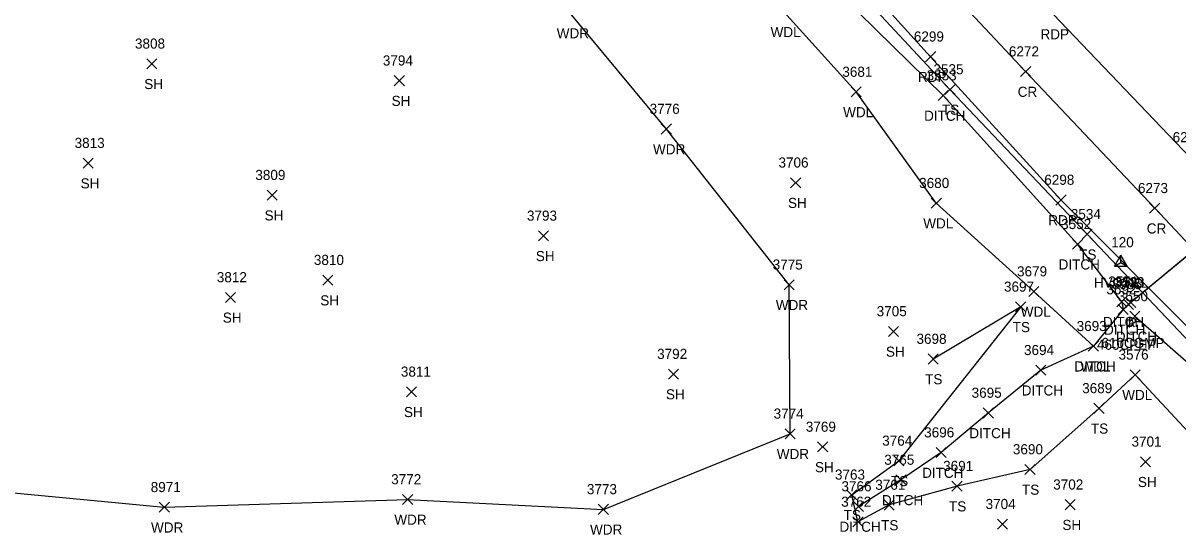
# Model space of a CAD drawing. Extents: x 1482574 to 1485769, y 580696 to 595649.
# Drawn here: x 1483954 to 1484182.5, y 582869.5 to 582970.7 of the extents above; entities that cross this region are included whole.
import ezdxf

# ---------------------------------------------------------------- set-up
doc = ezdxf.new("R2010")
doc.units = 0
for name, color, linetype in [('C_A', 7, 'Continuous'), ('C_I', 7, 'Continuous'), ('CPSM', 7, 'Continuous'), ('D_A', 7, 'Continuous'), ('D_C', 7, 'Continuous'), ('D_I', 7, 'Continuous'), ('D_TIC', 7, 'Continuous'), ('DCP', 7, 'Continuous'), ('DD', 7, 'Continuous'), ('L_A', 7, 'Continuous'), ('L_I', 7, 'Continuous'), ('L_TIC', 7, 'Continuous'), ('LABL', 7, 'Continuous'), ('LAWA', 7, 'Continuous'), ('LELB', 7, 'Continuous'), ('P_A', 7, 'Continuous'), ('P_I', 7, 'Continuous'), ('P_TIC', 7, 'Continuous'), ('PET', 7, 'Continuous'), ('PRC', 7, 'Continuous')]:
    doc.layers.add(name, color=color, linetype=linetype)

msp = doc.modelspace()

# ---------------------------------------------------------------- linework, layer by layer
at = {"layer": 'CPSM'}
for p, q in [((1484169.92, 582922.65), (1484171.17, 582924.82)), ((1484172.42, 582922.65), (1484171.17, 582924.82)), ((1484171.17, 582923.37), (1484171.17, 582924.82)), ((1484169.92, 582922.65), (1484171.17, 582923.37)), ((1484169.92, 582922.65), (1484172.42, 582922.65)), ((1484171.17, 582923.37), (1484171.17, 582923.37)), ((1484171.17, 582923.37), (1484172.42, 582922.65))]:
    msp.add_line(p, q, dxfattribs=at)
at = {"layer": 'D_TIC'}
for points in [[(1484135.02, 582955.39), (1484137.02, 582957.39)], [(1484137.02, 582955.39), (1484135.02, 582957.39)], [(1484161.64, 582925.97), (1484163.64, 582927.97)], [(1484163.64, 582925.97), (1484161.64, 582927.97)], [(1484170.4, 582914.6), (1484172.4, 582916.6)], [(1484172.4, 582914.6), (1484170.4, 582916.6)], [(1484171.69, 582914.09), (1484173.69, 582916.09)], [(1484173.69, 582914.09), (1484171.69, 582916.09)], [(1484172.17, 582914.45), (1484174.17, 582916.45)], [(1484174.17, 582914.45), (1484172.17, 582916.45)], [(1484170.63, 582913.07), (1484172.62, 582915.07)], [(1484172.62, 582913.07), (1484170.63, 582915.07)], [(1484172.95, 582911.7), (1484174.95, 582913.7)], [(1484174.95, 582911.7), (1484172.95, 582913.7)], [(1484164.75, 582905.79), (1484166.75, 582907.79)], [(1484166.75, 582905.79), (1484164.75, 582907.79)], [(1484154.34, 582901.04), (1484156.34, 582903.04)], [(1484156.34, 582901.04), (1484154.34, 582903.04)], [(1484143.98, 582892.59), (1484145.98, 582894.59)], [(1484145.98, 582892.59), (1484143.98, 582894.59)], [(1484134.64, 582884.75), (1484136.64, 582886.75)], [(1484136.64, 582884.75), (1484134.64, 582886.75)], [(1484126.69, 582879.34), (1484128.69, 582881.34)], [(1484128.69, 582879.34), (1484126.69, 582881.34)], [(1484118.28, 582874.08), (1484120.28, 582876.08)], [(1484120.28, 582874.08), (1484118.28, 582876.08)]]:
    msp.add_lwpolyline(points, dxfattribs=at)
at = {"layer": 'DCP'}
for points in [[(1484172.69, 582915.09), (1484207.11, 582943.53)], [(1484203.91, 582940.91), (1484173.17, 582915.45)]]:
    msp.add_lwpolyline(points, dxfattribs=at)
at = {"layer": 'DD'}
for points in [[(1484171.4, 582915.6), (1484162.64, 582926.97), (1484136.02, 582956.39), (1484105.95, 582985.95), (1484078.03, 583016.39), (1484050.41, 583045.09), (1484023.91, 583073.18), (1484012.19, 583086.75)], [(1484171.4, 582915.6), (1484171.62, 582914.07)], [(1484171.62, 582914.07), (1484165.75, 582906.79), (1484155.34, 582902.04), (1484144.98, 582893.59), (1484135.64, 582885.75), (1484127.69, 582880.34), (1484119.28, 582875.08)], [(1484400.87, 582726.9), (1484383.65, 582732.27), (1484351.97, 582747.1), (1484327.02, 582760.95), (1484298.61, 582786.76), (1484268.65, 582815.14), (1484241.89, 582844.67), (1484214.72, 582873.05), (1484187.35, 582900.96), (1484173.95, 582912.7)]]:
    msp.add_lwpolyline(points, dxfattribs=at)
at = {"layer": 'L_TIC'}
for points in [[(1483978.5, 582961.67), (1483980.5, 582963.67)], [(1483980.5, 582961.67), (1483978.5, 582963.67)], [(1484027.45, 582958.33), (1484029.45, 582960.33)], [(1484029.45, 582958.33), (1484027.45, 582960.33)], [(1484117.83, 582956.1), (1484119.83, 582958.09)], [(1484119.83, 582956.1), (1484117.83, 582958.09)], [(1484136.38, 582956.59), (1484138.38, 582958.59)], [(1484138.38, 582956.59), (1484136.38, 582958.59)], [(1484080.28, 582948.76), (1484082.28, 582950.76)], [(1484082.28, 582948.76), (1484080.28, 582950.76)], [(1483965.92, 582942.02), (1483967.92, 582944.02)], [(1483967.92, 582942.02), (1483965.92, 582944.02)], [(1484105.85, 582938.14), (1484107.85, 582940.14)], [(1484107.85, 582938.14), (1484105.85, 582940.14)], [(1484002.32, 582935.68), (1484004.32, 582937.68)], [(1484004.32, 582935.68), (1484002.32, 582937.68)], [(1484133.68, 582934.09), (1484135.68, 582936.09)], [(1484135.68, 582934.09), (1484133.68, 582936.09)], [(1484055.96, 582927.63), (1484057.96, 582929.63)], [(1484057.96, 582927.63), (1484055.96, 582929.63)], [(1484163.54, 582927.94), (1484165.54, 582929.94)], [(1484165.54, 582927.94), (1484163.54, 582929.94)], [(1484013.33, 582918.87), (1484015.33, 582920.87)], [(1484015.33, 582918.87), (1484013.33, 582920.87)], [(1484104.57, 582917.95), (1484106.57, 582919.95)], [(1484106.57, 582917.95), (1484104.57, 582919.95)], [(1484152.96, 582916.61), (1484154.96, 582918.61)], [(1484154.96, 582916.61), (1484152.96, 582918.61)], [(1484152.96, 582916.61), (1484154.96, 582918.61)], [(1484154.96, 582916.61), (1484152.96, 582918.61)], [(1483994.04, 582915.45), (1483996.04, 582917.45)], [(1483996.04, 582915.45), (1483994.04, 582917.45)], [(1484150.38, 582913.58), (1484152.38, 582915.58)], [(1484152.38, 582913.58), (1484150.38, 582915.58)], [(1484125.22, 582908.72), (1484127.22, 582910.72)], [(1484127.22, 582908.72), (1484125.22, 582910.72)], [(1484164.75, 582905.79), (1484166.75, 582907.79)], [(1484166.75, 582905.79), (1484164.75, 582907.79)], [(1484133.06, 582903.26), (1484135.06, 582905.26)], [(1484135.06, 582903.26), (1484133.06, 582905.26)], [(1484081.71, 582900.28), (1484083.71, 582902.27)], [(1484083.71, 582900.28), (1484081.71, 582902.27)], [(1484173.04, 582900.15), (1484175.04, 582902.15)], [(1484175.04, 582900.15), (1484173.04, 582902.15)], [(1484029.88, 582896.77), (1484031.88, 582898.77)], [(1484031.88, 582896.77), (1484029.88, 582898.77)], [(1484165.86, 582893.5), (1484167.86, 582895.5)], [(1484167.86, 582893.5), (1484165.86, 582895.5)], [(1484104.76, 582888.47), (1484106.76, 582890.47)], [(1484106.76, 582888.47), (1484104.76, 582890.47)], [(1484111.19, 582885.87), (1484113.19, 582887.87)], [(1484113.19, 582885.87), (1484111.19, 582887.87)], [(1484126.29, 582883.11), (1484128.29, 582885.11)], [(1484128.29, 582883.11), (1484126.29, 582885.11)], [(1484175.07, 582882.93), (1484177.07, 582884.93)], [(1484177.07, 582882.93), (1484175.07, 582884.93)], [(1484152.22, 582881.41), (1484154.22, 582883.41)], [(1484154.22, 582881.41), (1484152.22, 582883.41)], [(1484137.78, 582878.11), (1484139.78, 582880.11)], [(1484139.78, 582878.11), (1484137.78, 582880.11)], [(1484029.1, 582875.49), (1484031.1, 582877.48)], [(1484031.1, 582875.49), (1484029.1, 582877.48)], [(1484116.94, 582876.4), (1484118.94, 582878.4)], [(1484118.94, 582876.4), (1484116.94, 582878.4)], [(1483980.96, 582873.93), (1483982.96, 582875.93)], [(1483982.96, 582873.93), (1483980.96, 582875.93)], [(1484067.82, 582873.52), (1484069.82, 582875.52)], [(1484069.82, 582873.52), (1484067.82, 582875.52)], [(1484124.35, 582874.38), (1484126.35, 582876.38)], [(1484126.35, 582874.38), (1484124.35, 582876.38)], [(1484160.15, 582874.45), (1484162.15, 582876.44)], [(1484162.15, 582874.45), (1484160.15, 582876.44)], [(1484118.18, 582871.03), (1484120.18, 582873.03)], [(1484120.18, 582871.03), (1484118.18, 582873.03)], [(1484146.77, 582870.58), (1484148.77, 582872.58)], [(1484148.77, 582870.58), (1484146.77, 582872.58)]]:
    msp.add_lwpolyline(points, dxfattribs=at)
at = {"layer": 'LABL'}
msp.add_lwpolyline([(1483947.92, 582878.18), (1483981.96, 582874.93)], dxfattribs=at)
at = {"layer": 'LAWA'}
for points in [[(1484030.1, 582876.48), (1484068.82, 582874.52), (1484105.76, 582889.47), (1484105.57, 582918.95), (1484081.28, 582949.76), (1484062.23, 582972.71), (1484033.59, 583003.27), (1484005.46, 583038.35), (1483989.3, 583058.08), (1483962.79, 583084.49), (1483933.09, 583114.83), (1483908.74, 583144.04), (1483882.23, 583166.93), (1483868.61, 583172.26)], [(1484153.96, 582917.61), (1484134.68, 582935.09), (1484118.83, 582957.09), (1484104.49, 582972.93), (1484091.89, 582987.87), (1484079.75, 582997.92), (1484068.28, 583011), (1484047.87, 583032.86), (1484030.91, 583051.96), (1484004.4, 583078.79)], [(1484153.96, 582917.61), (1484165.75, 582906.79)], [(1484191.87, 582821.82), (1484229.21, 582818.01), (1484245.75, 582826.08), (1484219.74, 582845.54), (1484205.23, 582866.51), (1484188.09, 582886.02), (1484174.04, 582901.15)], [(1483981.96, 582874.93), (1484030.1, 582876.48)]]:
    msp.add_lwpolyline(points, dxfattribs=at)
at = {"layer": 'LELB'}
for points in [[(1484402.9, 582726.21), (1484402.79, 582730.01), (1484384.34, 582736.92), (1484350.52, 582752.18), (1484323.04, 582770.42), (1484293.61, 582794.8), (1484265.96, 582821.75), (1484239.84, 582849.66), (1484213.41, 582877.57), (1484187.41, 582904.81), (1484164.54, 582928.94), (1484137.38, 582957.59), (1484109.3, 582987.71), (1484082.7, 583016.6), (1484054.89, 583044.87), (1484027.97, 583073.07), (1484014.36, 583088.28)], [(1484151.38, 582914.58), (1484127.29, 582884.11)], [(1484151.38, 582914.58), (1484134.06, 582904.26)], [(1484166.86, 582894.5), (1484174.04, 582901.15)], [(1484166.86, 582894.5), (1484153.22, 582882.41), (1484138.78, 582879.11)], [(1484125.35, 582875.38), (1484119.18, 582872.03), (1484117.94, 582877.4), (1484127.29, 582884.11)], [(1484138.78, 582879.11), (1484125.35, 582875.38)]]:
    msp.add_lwpolyline(points, dxfattribs=at)
at = {"layer": 'P_TIC'}
for points in [[(1484132.56, 582963.07), (1484134.56, 582965.07)], [(1484134.56, 582963.07), (1484132.56, 582965.07)], [(1484151.35, 582960.13), (1484153.35, 582962.13)], [(1484153.35, 582960.13), (1484151.35, 582962.13)], [(1484158.34, 582934.73), (1484160.34, 582936.73)], [(1484160.34, 582934.73), (1484158.34, 582936.73)], [(1484176.88, 582933.09), (1484178.88, 582935.09)], [(1484178.88, 582933.09), (1484176.88, 582935.09)]]:
    msp.add_lwpolyline(points, dxfattribs=at)
at = {"layer": 'PET'}
for points in [[(1484491.08, 582753.94), (1484493.22, 582746.26), (1484462.76, 582739.1), (1484431.88, 582736.4), (1484400.51, 582737.99), (1484369.56, 582746.76), (1484340.37, 582760.44), (1484314.77, 582778.92), (1484290.06, 582800.8), (1484263.27, 582827.56), (1484237.31, 582854.83), (1484211.32, 582882.47), (1484185.75, 582909.27), (1484159.34, 582935.73), (1484133.56, 582964.07), (1484107.83, 582992.49), (1484081.64, 583020.87), (1484054.98, 583048.7), (1484028.69, 583076.2), (1484015.92, 583089.84)], [(1484488.73, 582762.43), (1484458.42, 582759.47), (1484428.1, 582761.56), (1484397.39, 582767.41), (1484367.33, 582777), (1484339.02, 582792.83), (1484318.92, 582808.53), (1484293.05, 582832.28), (1484266.16, 582858.48), (1484239.66, 582886.48), (1484211.15, 582916.1), (1484184.88, 582944.15), (1484157.81, 582972.51), (1484130.84, 583000.7), (1484106.21, 583027.51), (1484077.55, 583057.77), (1484051.19, 583086.4)]]:
    msp.add_lwpolyline(points, dxfattribs=at)
at = {"layer": 'PRC'}
msp.add_lwpolyline([(1484049.41, 583070.99), (1484075.46, 583043.5), (1484101.38, 583015.76), (1484126.34, 582988.92), (1484152.35, 582961.13), (1484177.88, 582934.09), (1484203.24, 582907.12), (1484228.69, 582880.03), (1484254.53, 582852.85), (1484280.74, 582825.88), (1484302.69, 582805.16), (1484325.66, 582786.45), (1484351.27, 582770.37), (1484379.25, 582758.35), (1484409.57, 582750.74), (1484442.81, 582748.51), (1484469.16, 582749.53), (1484491.08, 582753.94)], dxfattribs=at)

# ---------------------------------------------------------------- texts
at = {"layer": 'C_A'}
msp.add_text('HVCTRL', height=2, dxfattribs=at).set_placement((1484165.86, 582918.37))
at = {"layer": 'C_I'}
msp.add_text('120', height=2, dxfattribs=at).set_placement((1484169.28, 582926.37))
at = {"layer": 'D_A'}
for s, p in [('DITCH', (1484132.26, 582951.39)), ('DITCH', (1484158.88, 582921.97)), ('DITCH', (1484167.63, 582910.6)), ('DITCH', (1484167.86, 582909.07)), ('P', (1484172.06, 582910.09)), ('P', (1484172.55, 582910.45)), ('DITCH', (1484170.19, 582907.7)), ('DITCH', (1484161.99, 582901.79)), ('DITCH', (1484151.58, 582897.04)), ('DITCH', (1484141.21, 582888.59)), ('DITCH', (1484131.88, 582880.75)), ('DITCH', (1484123.92, 582875.34)), ('DITCH', (1484115.52, 582870.08))]:
    msp.add_text(s, height=2, dxfattribs=at).set_placement(p)
at = {"layer": 'D_C'}
for s, p in [('460CPEP', (1484166.46, 582906.09)), ('610CGMP', (1484167.34, 582906.45))]:
    msp.add_text(s, height=2, dxfattribs=at).set_placement(p)
at = {"layer": 'D_I'}
for s, p in [('3553', (1484132.76, 582959.39)), ('3552', (1484159.38, 582929.97)), ('3551', (1484168.71, 582918.6)), ('8985', (1484169.43, 582918.09)), ('3523', (1484169.91, 582918.45)), ('3692', (1484168.32, 582917.07)), ('3550', (1484170.61, 582915.7)), ('3693', (1484162.44, 582909.79)), ('3694', (1484152.03, 582905.04)), ('3695', (1484141.67, 582896.59)), ('3696', (1484132.28, 582888.75)), ('3765', (1484124.38, 582883.34)), ('3766', (1484115.92, 582878.08))]:
    msp.add_text(s, height=2, dxfattribs=at).set_placement(p)
at = {"layer": 'L_A'}
for s, p in [('WDR', (1484059.59, 582967.71)), ('WDL', (1484101.9, 582967.94)), ('SH', (1483977.99, 582957.67)), ('SH', (1484026.93, 582954.33)), ('TS', (1484135.79, 582952.59)), ('WDL', (1484116.25, 582952.09)), ('WDR', (1484078.64, 582944.76)), ('SH', (1483965.41, 582938.02)), ('SH', (1484105.34, 582934.14)), ('SH', (1484001.8, 582931.68)), ('WDL', (1484132.1, 582930.09)), ('SH', (1484055.45, 582923.63)), ('TS', (1484162.95, 582923.94)), ('SH', (1484012.82, 582914.87)), ('WDR', (1484102.93, 582913.95)), ('SH', (1483993.53, 582911.45)), ('WDL', (1484151.38, 582912.61)), ('WDL', (1484151.38, 582912.61)), ('TS', (1484149.79, 582909.58)), ('SH', (1484124.71, 582904.72)), ('WDL', (1484163.17, 582901.79)), ('TS', (1484132.47, 582899.26)), ('SH', (1484081.2, 582896.28)), ('WDL', (1484171.46, 582896.15)), ('SH', (1484029.37, 582892.77)), ('TS', (1484165.27, 582889.5)), ('WDR', (1484103.12, 582884.47)), ('SH', (1484110.68, 582881.87)), ('TS', (1484125.7, 582879.11)), ('TS', (1484151.63, 582877.41)), ('SH', (1484174.56, 582878.93)), ('TS', (1484116.35, 582872.4)), ('TS', (1484137.19, 582874.11)), ('WDR', (1484027.47, 582871.48)), ('TS', (1484123.76, 582870.38)), ('SH', (1484159.63, 582870.44)), ('WDR', (1483979.33, 582869.93)), ('WDR', (1484066.18, 582869.52))]:
    msp.add_text(s, height=2, dxfattribs=at).set_placement(p)
at = {"layer": 'L_I'}
for s, p in [('3808', (1483976.16, 582965.67)), ('3794', (1484025.19, 582962.33)), ('3681', (1484116.09, 582960.09)), ('3535', (1484134.12, 582960.59)), ('3776', (1484077.97, 582952.76)), ('3813', (1483964.22, 582946.02)), ('3706', (1484103.46, 582942.14)), ('3809', (1483999.97, 582939.68)), ('3680', (1484131.29, 582938.09)), ('3534', (1484161.29, 582931.94)), ('3793', (1484053.7, 582931.63)), ('3810', (1484011.55, 582922.87)), ('3775', (1484102.31, 582921.95)), ('3679', (1484150.65, 582920.61)), ('3679', (1484150.65, 582920.61)), ('3812', (1483992.35, 582919.45)), ('3697', (1484148.07, 582917.58)), ('3705', (1484122.88, 582912.72)), ('3693', (1484162.44, 582909.79)), ('3698', (1484130.76, 582907.26)), ('3792', (1484079.45, 582904.28)), ('3576', (1484170.73, 582904.15)), ('3811', (1484028.76, 582900.77)), ('3689', (1484163.54, 582897.5)), ('3774', (1484102.5, 582892.47)), ('3769', (1484108.87, 582889.87)), ('3764', (1484123.98, 582887.11)), ('3701', (1484173.3, 582886.93)), ('3690', (1484149.83, 582885.41)), ('3691', (1484136.04, 582882.11)), ('3772', (1484026.84, 582879.48)), ('3763', (1484114.63, 582880.4)), ('8971', (1483979.27, 582877.93)), ('3773', (1484065.56, 582877.52)), ('3761', (1484122.61, 582878.38)), ('3702', (1484157.81, 582878.44)), ('3762', (1484115.87, 582875.03)), ('3704', (1484144.43, 582874.58))]:
    msp.add_text(s, height=2, dxfattribs=at).set_placement(p)
at = {"layer": 'P_A'}
for s, p in [('RDP', (1484155.29, 582967.51)), ('RDP', (1484131.05, 582959.07)), ('CR', (1484150.78, 582956.13)), ('RDP', (1484156.83, 582930.73)), ('CR', (1484176.31, 582929.09))]:
    msp.add_text(s, height=2, dxfattribs=at).set_placement(p)
at = {"layer": 'P_I'}
for s, p in [('6299', (1484130.24, 582967.07)), ('6272', (1484149.04, 582964.13)), ('6260', (1484181.44, 582947.15)), ('6298', (1484156.04, 582938.73)), ('6273', (1484174.57, 582937.09))]:
    msp.add_text(s, height=2, dxfattribs=at).set_placement(p)

doc.saveas('drawing.dxf')
